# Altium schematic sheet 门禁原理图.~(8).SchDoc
size D
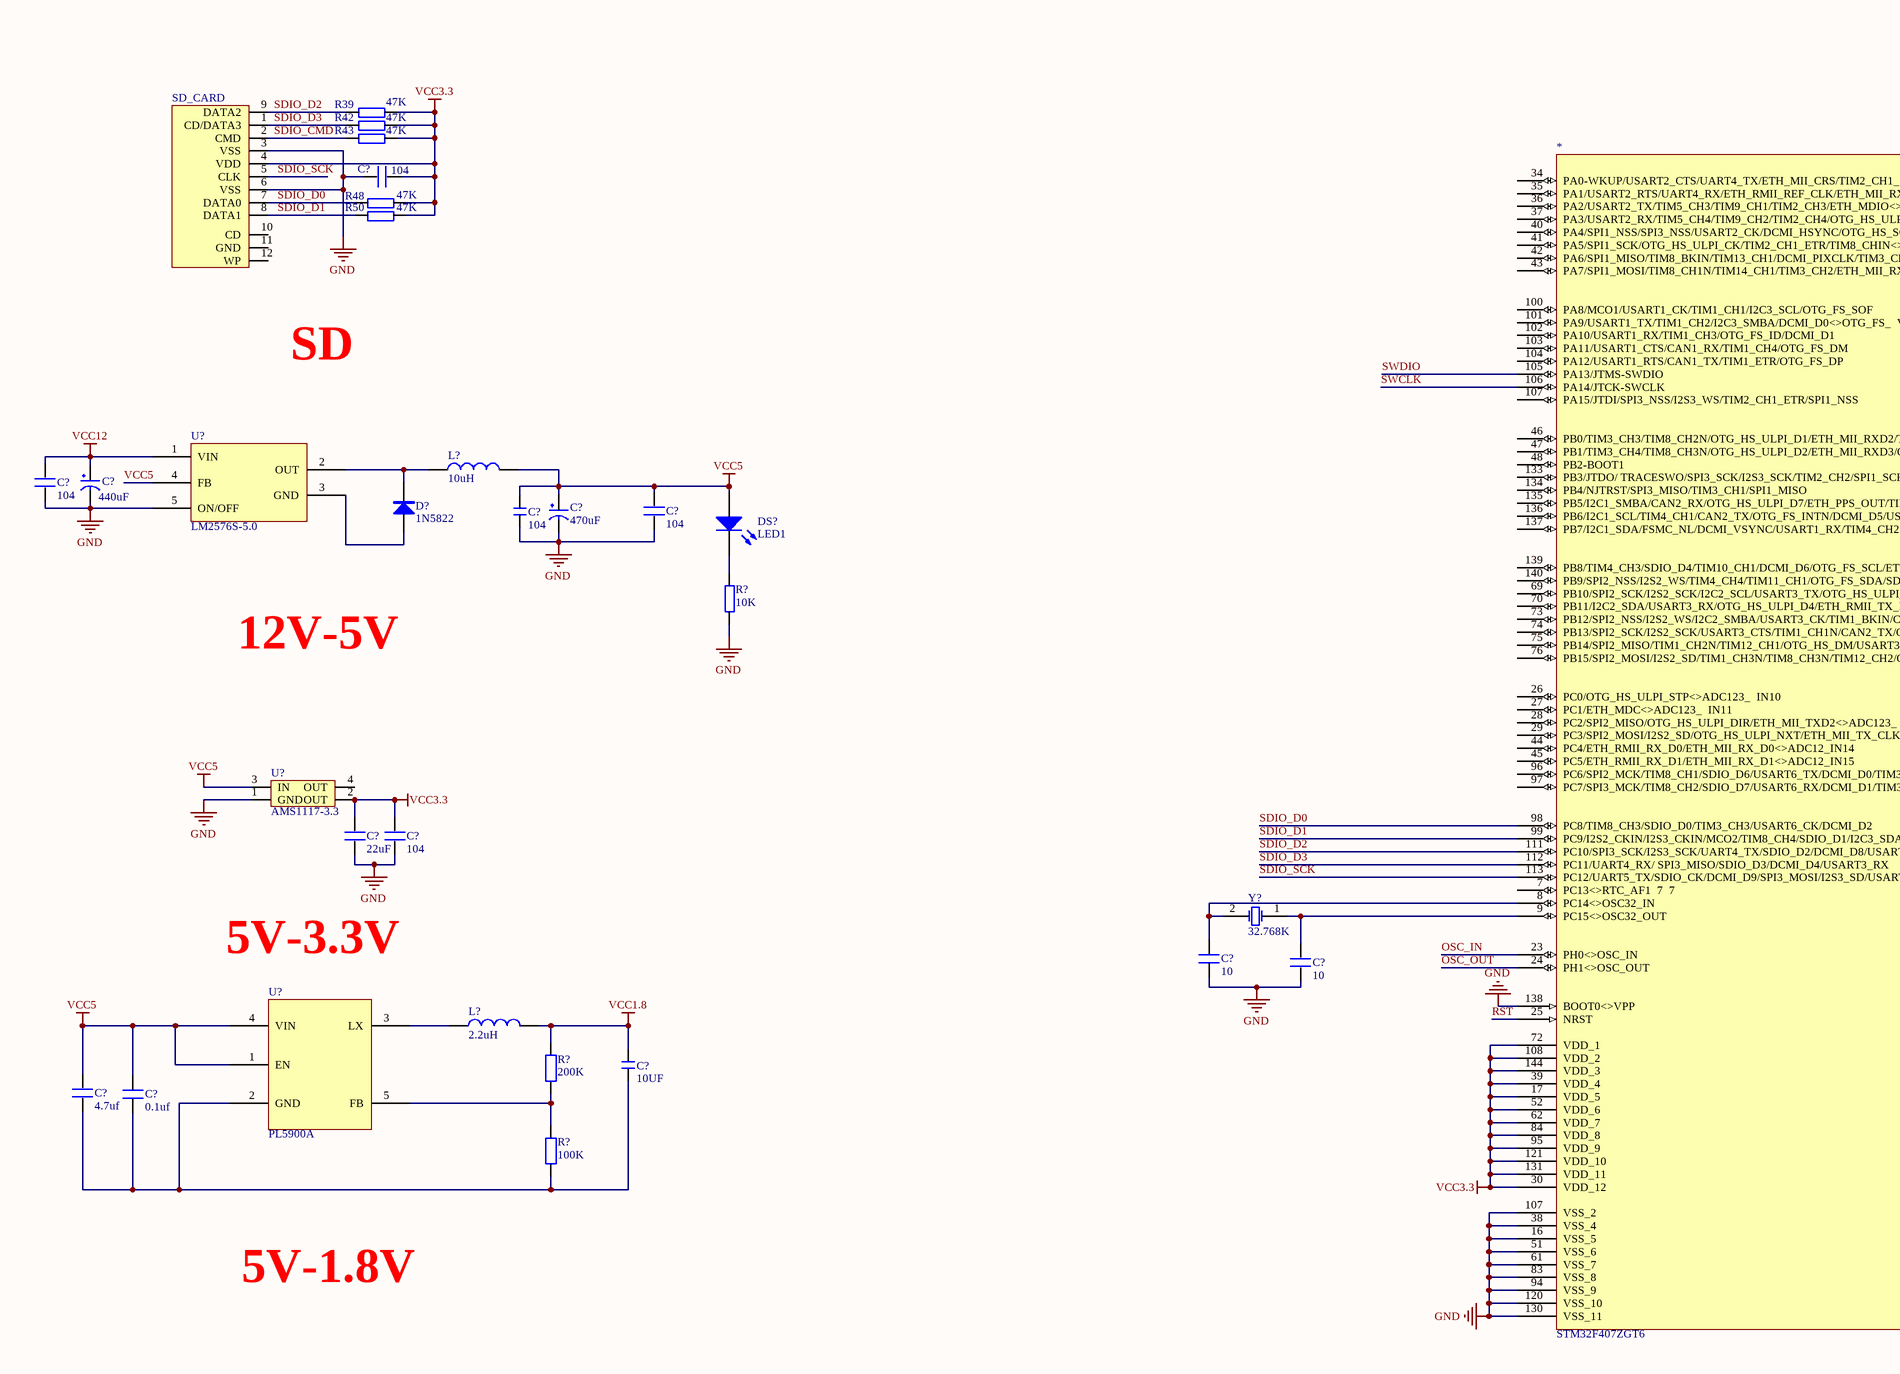
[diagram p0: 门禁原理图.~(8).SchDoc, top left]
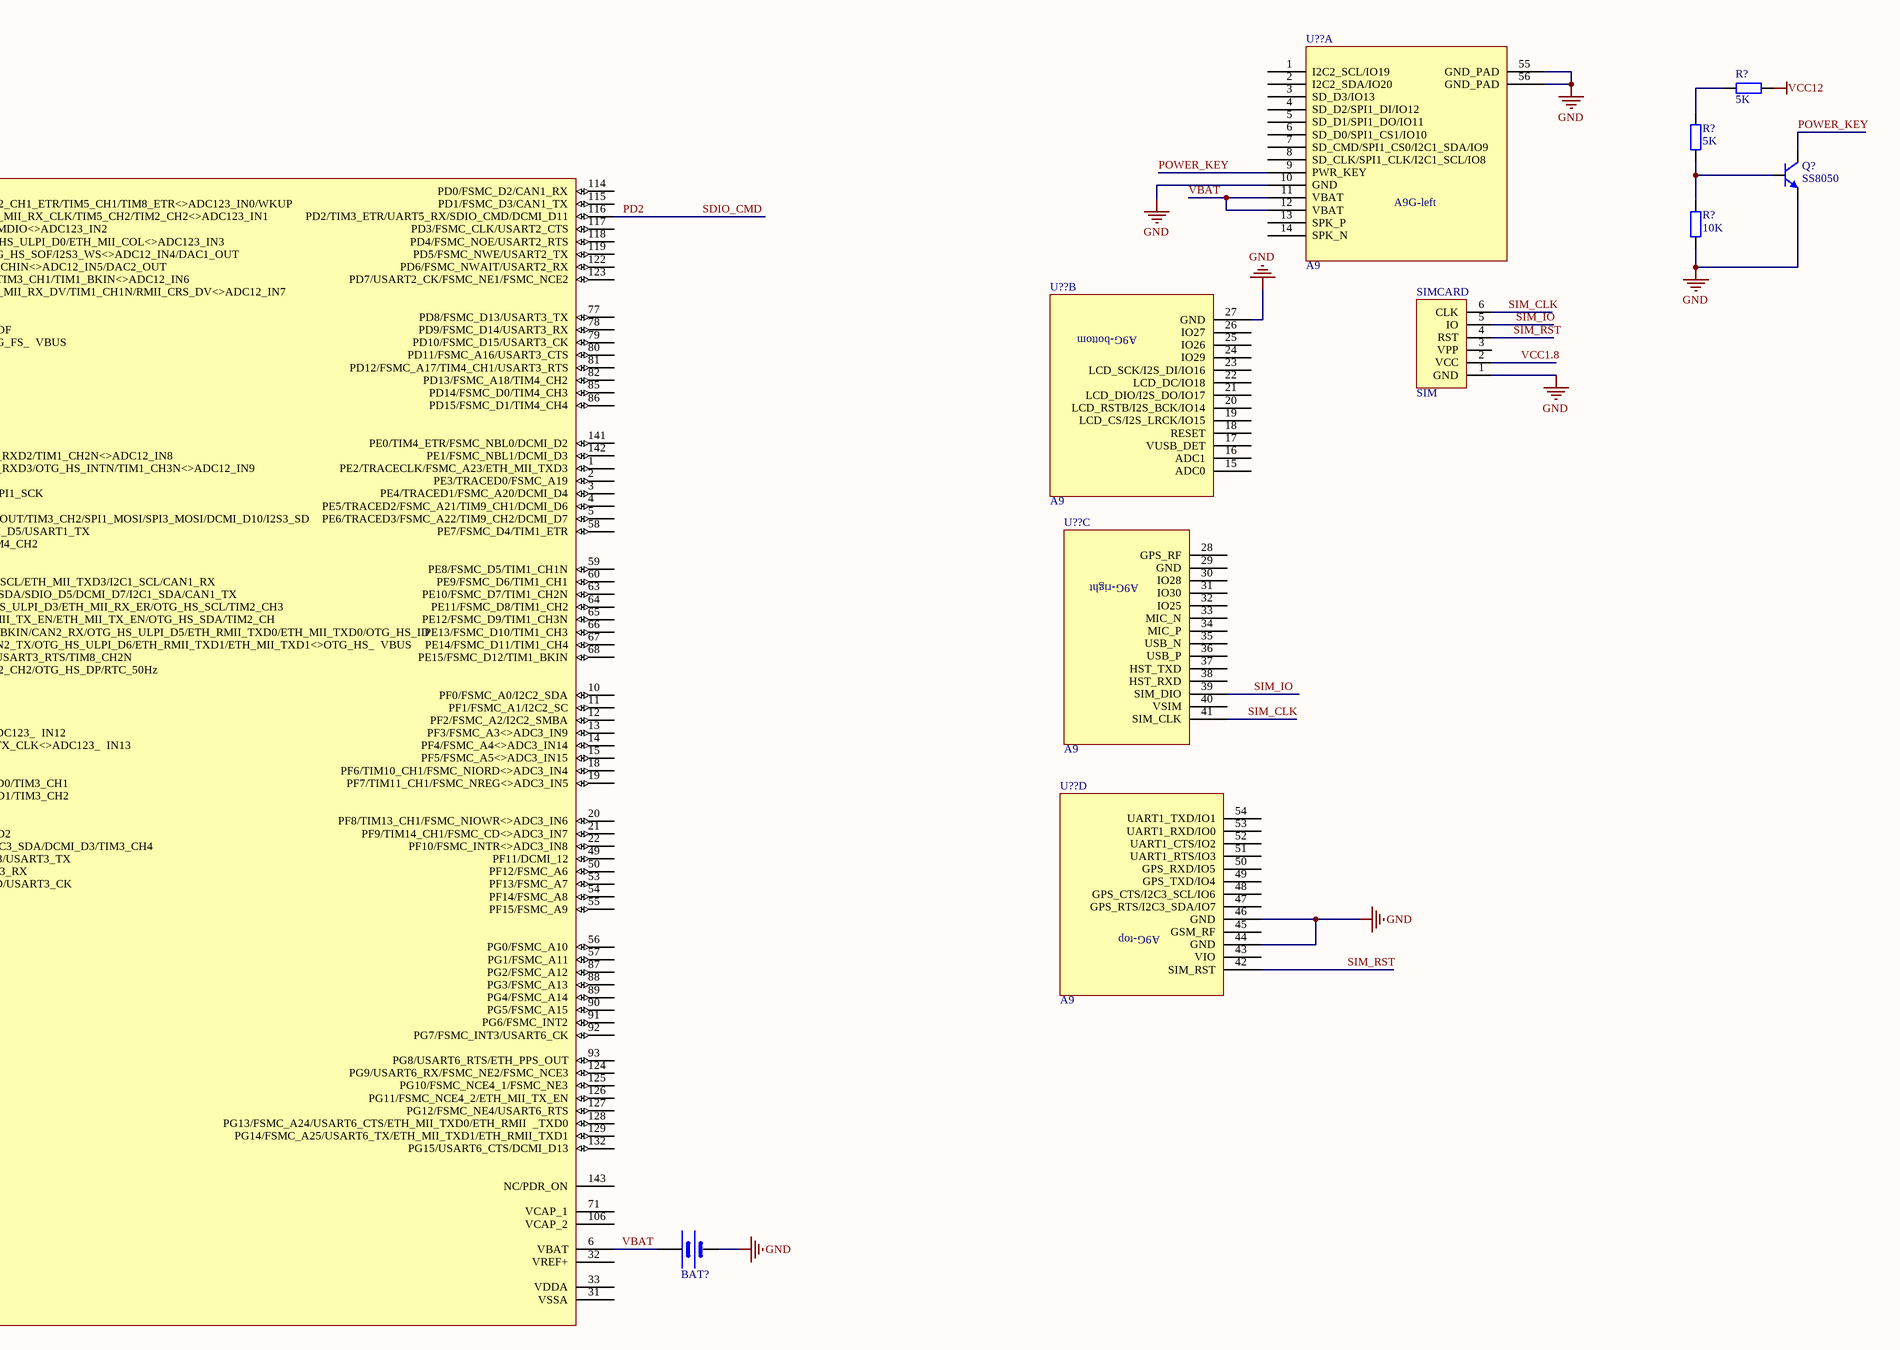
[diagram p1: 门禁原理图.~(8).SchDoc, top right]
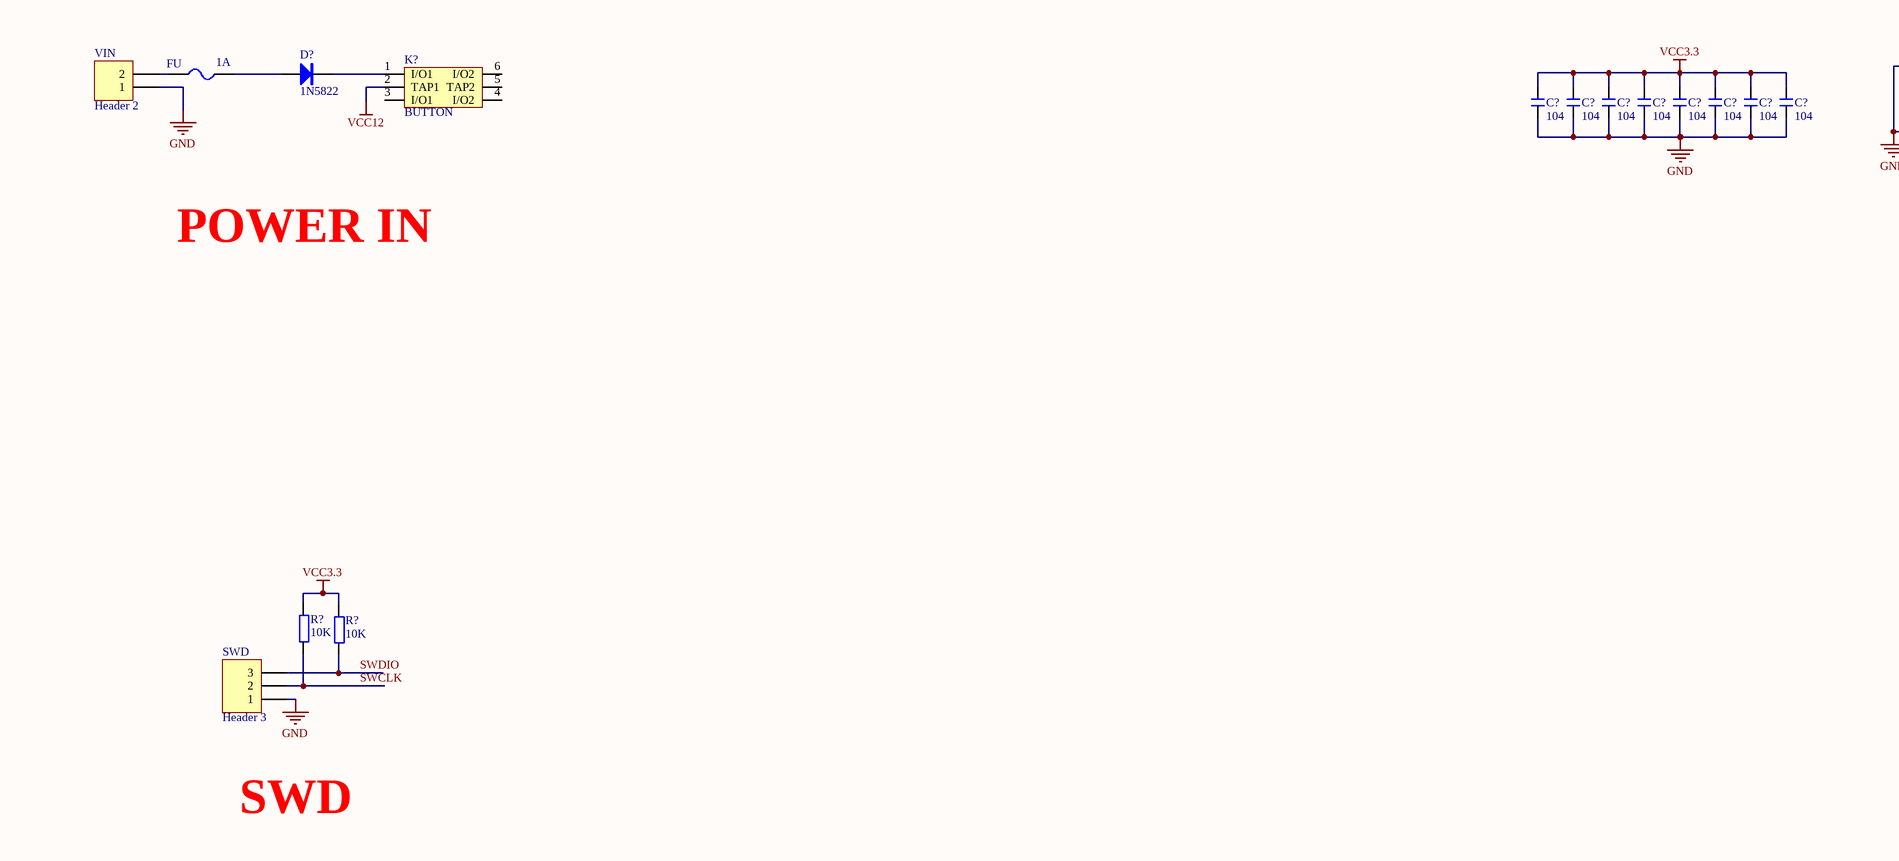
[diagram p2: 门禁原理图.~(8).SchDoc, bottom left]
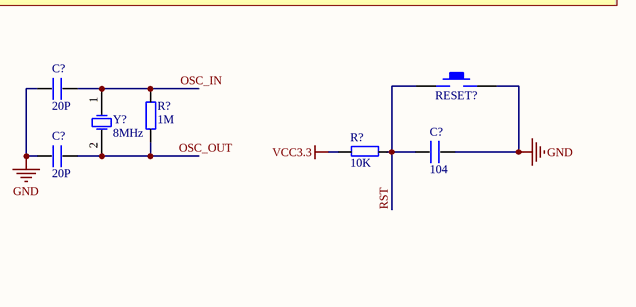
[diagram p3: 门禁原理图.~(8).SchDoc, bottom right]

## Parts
(Parts that share a designator on the sheet are numbered #1, #2 ... from top to bottom, then left to right.)
*  STM32F407ZGT6
BAT?  BATT  [BATM]  (value not drawn)
C?#1  104  [0603P]
C?#2  440uF  [CC6.56.5]
C?#3  104  [C 0805_L]
C?#4  470uF  [CC6.56.5]
C?#5  104  [0603P]
C?#6  104  [0805]
C?#7  10  [0603P]
C?#8  22uF  [0603P]
C?#9  104  [0603P]
C?#10  10  [0603P]
C?#11  10UF  [C 0805_L]
C?#12  4.7uf  [0603P]
C?#13  0.1uf  [0603P]
C?#14  20P  [0805]
C?#15  20P  [0805]
C?#16  104  [C 0805_L]
C?#17  104  [C 0805_L]
C?#18  104  [C 0805_L]
C?#19  104  [C 0805_L]
C?#20  104  [C 0805_L]
C?#21  104  [C 0805_L]
C?#22  104  [C 0805_L]
C?#23  104  [C 0805_L]
C?#24  104  [0805]
D?#1  1N5822  [DIODE_3*5.3]
D?#2  1N5822  [DIODE_3*5.3]
DS?  LED1  [SMDLED]
FU  1A  [FU 1812]
K?  BUTTON  [BTN8.5*8.5]
L?#1  10uH  [L 0805]
L?#2  2.2uH  [L 0805]
Q?  SS8050  [SOT23-3N]
R39  47K  [0603P]
R42  47K  [0603P]
R43  47K  [0603P]
R48  47K  [0603P]
R50  47K  [0603P]
R?#1  5K  [R 0805_L]
R?#2  5K  [R 0805_L]
R?#3  10K  [R 0805_L]
R?#4  10K  [0805]
R?#5  200K  [R 0805_L]
R?#6  100K  [R 0805_L]
R?#7  10K  [0805]
R?#8  1M  [0805]
R?#9  10K  [0805]
R?#10  10K  [0805]
RESET?  KEY_M  [KEY_M]  (value not drawn)
SD_CARD  sd card  [SDCARD_L]  (value not drawn)
SIMCARD  SIM  [MICRO SIM]
SWD  Header 3  [HDR1X3]
U?#1  LM2576S-5.0  [TO263-5A]
U?#2  AMS1117-3.3  [AMS1117]
U?#3  PL5900A  [SOT23-5L]
U??#1  A9  [A9]  (part A of 4)
U??#2  A9  [A9]  (part B of 4)
U??#3  A9  [A9]  (part C of 4)
U??#4  A9  [A9]  (part D of 4)
VIN  Header 2  [HDR1X2]
Y?#1  32.768K  [XTAL32]
Y?#2  8MHz  [XTAL_US]

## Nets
GND: *.16(VSS_5) *.38(VSS_4) *.51(VSS_6) *.61(VSS_7) *.83(VSS_8) *.94(VSS_9) *.107(PA15/JTDI/SPI3_NSS/I2S3_WS/TIM2_CH1_ETR/SPI1_NSS) *.120(VSS_10) *.130(VSS_11) *.138(BOOT0<>VPP) BAT?.2(GND) C?#1.1 C?#2.2(GND) C?#3.1 C?#4.2(GND) C?#5.1 C?#6.1 C?#7.2 C?#8.1 C?#9.1 C?#10.1 C?#14.1 C?#15.1 C?#16.1 C?#17.1 C?#18.1 C?#19.1 C?#20.1 C?#21.1 C?#22.1 C?#23.1 C?#24.1 Q?.2(E) R?#3.1 R?#4.1 RESET?.2 SD_CARD.3(VSS) SD_CARD.6(VSS) SIMCARD.1(GND) SWD.1 U?#1.5(ON/OFF) U?#2.1(GND) U??#1.10(GND) U??#1.55(GND_PAD) U??#1.56(GND_PAD) U??#2.27(GND) U??#4.44(GND) U??#4.46(GND) VIN.1
VCC1.8: C?#11.2 L?#2.2 R?#5.2 SIMCARD.2(VCC)
VCC3.3: *.17(VDD_5) *.30(VDD_12) *.39(VDD_4) *.52(VDD_6) *.62(VDD_7) *.72(VDD_1) *.84(VDD_8) *.95(VDD_9) *.108(VDD_2) *.121(VDD_10) *.131(VDD_11) *.144(VDD_3) C?#1.2 C?#8.2 C?#9.2 C?#16.2 C?#17.2 C?#18.2 C?#19.2 C?#20.2 C?#21.2 C?#22.2 C?#23.2 R39.2 R42.2 R43.2 R48.2 R50.2 R?#7.2 R?#9.2 R?#10.2 SD_CARD.4(VDD) U?#2.2(OUT)
VCC5: C?#3.2 C?#4.1(VCC) C?#6.2 C?#12.2 C?#13.2 DS?.1(A) L?#1.2 U?#1.4(FB) U?#2.3(IN) U?#3.1(EN) U?#3.4(VIN)
VCC12: C?#2.1(VCC) C?#5.2 K?.2(TAP1) R?#1.1 U?#1.1(VIN)
OSC_IN: *.23(PH0<>OSC_IN) C?#14.2 R?#8.2 Y?#2.1(OSC1)
OSC_OUT: *.24(PH1<>OSC_OUT) C?#15.2 R?#8.1 Y?#2.2(OSC2)
PD2: *.116(PD2/TIM3_ETR/UART5_RX/SDIO_CMD/DCMI_D11) R43.1 SD_CARD.2(CMD)  [also labelled SDIO_CMD]
POWER_KEY: Q?.3(C) U??#1.9(PWR_KEY)
RST: *.25(NRST) C?#24.2 R?#7.1 RESET?.1
SDIO_D0: *.98(PC8/TIM8_CH3/SDIO_D0/TIM3_CH3/USART6_CK/DCMI_D2) R48.1 SD_CARD.7(DATA0)
SDIO_D1: *.99(PC9/I2S2_CKIN/I2S3_CKIN/MCO2/TIM8_CH4/SDIO_D1/I2C3_SDA/DCMI_D3/TIM3_CH4) R50.1 SD_CARD.8(DATA1)
SDIO_D2: *.111(PC10/SPI3_SCK/I2S3_SCK/UART4_TX/SDIO_D2/DCMI_D8/USART3_TX) R39.1 SD_CARD.9(DATA2)
SDIO_D3: *.112(PC11/UART4_RX/_SPI3_MISO/SDIO_D3/DCMI_D4/USART3_RX) R42.1 SD_CARD.1(CD/DATA3)
SDIO_SCK: *.113(PC12/UART5_TX/SDIO_CK/DCMI_D9/SPI3_MOSI/I2S3_SD/USART3_CK) SD_CARD.5(CLK)
SIM_CLK: SIMCARD.6(CLK) U??#3.41(SIM_CLK)
SIM_IO: SIMCARD.5(IO) U??#3.39(SIM_DIO)
SIM_RST: SIMCARD.4(RST) U??#4.42(SIM_RST)
SWCLK: *.106(PA14/JTCK-SWCLK) R?#9.1 SWD.2
SWDIO: *.105(PA13/JTMS-SWDIO) R?#10.1 SWD.3
VBAT: *.6(VBAT) BAT?.1(VCC) U??#1.11(VBAT) U??#1.12(VBAT)
Net*_8: *.8(PC14<>OSC32_IN) C?#7.1 Y?#1.2(OSC2)
Net*_9: *.9(PC15<>OSC32_OUT) C?#10.2 Y?#1.1(OSC1)
NetC?#11_1: C?#11.1 C?#12.1 C?#13.1 R?#6.1 U?#3.2(GND)
NetD?#1_1: D?#1.1(A) U?#1.3(GND)
NetD?#1_2: D?#1.2(K) L?#1.1 U?#1.2(OUT)
NetD?#2_1: D?#2.1(A) FU.2
NetD?#2_2: D?#2.2(K) K?.1(I/O1)
NetDS?_2: DS?.2(K) R?#4.2
NetFU_1: FU.1 VIN.2
NetL?#2_1: L?#2.1 U?#3.3(LX)
NetQ?_1: Q?.1(B) R?#2.1 R?#3.2
NetR?#1_2: R?#1.2 R?#2.2
NetR?#5_1: R?#5.1 R?#6.2 U?#3.5(FB)

Not connected (* = marked no-connect by the designer): * 1(PE2/TRACECLK/FSMC_A23/ETH_MII_TXD3) 2(PE3/TRACED0/FSMC_A19) 3(PE4/TRACED1/FSMC_A20/DCMI_D4) 4(PE5/TRACED2/FSMC_A21/TIM9_CH1/DCMI_D6) 5(PE6/TRACED3/FSMC_A22/TIM9_CH2/DCMI_D7) 7(PC13<>RTC_AF1__7__7) 10(PF0/FSMC_A0/I2C2_SDA) 11(PF1/FSMC_A1/I2C2_SC) 12(PF2/FSMC_A2/I2C2_SMBA) 13(PF3/FSMC_A3<>ADC3_IN9) 14(PF4/FSMC_A4<>ADC3_IN14) 15(PF5/FSMC_A5<>ADC3_IN15) 18(PF6/TIM10_CH1/FSMC_NIORD<>ADC3_IN4) 19(PF7/TIM11_CH1/FSMC_NREG<>ADC3_IN5) 20(PF8/TIM13_CH1/FSMC_NIOWR<>ADC3_IN6) 21(PF9/TIM14_CH1/FSMC_CD<>ADC3_IN7) 22(PF10/FSMC_INTR<>ADC3_IN8) 26(PC0/OTG_HS_ULPI_STP<>ADC123___IN10) 27(PC1/ETH_MDC<>ADC123___IN11) 28(PC2/SPI2_MISO/OTG_HS_ULPI_DIR/ETH_MII_TXD2<>ADC123___IN12) 29(PC3/SPI2_MOSI/I2S2_SD/OTG_HS_ULPI_NXT/ETH_MII_TX_CLK<>ADC123___IN13) 31(VSSA) 32(VREF+) 33(VDDA) 34(PA0-WKUP/USART2_CTS/UART4_TX/ETH_MII_CRS/TIM2_CH1_ETR/TIM5_CH1/TIM8_ETR<>ADC123_IN0/WKUP) 35(PA1/USART2_RTS/UART4_RX/ETH_RMII_REF_CLK/ETH_MII_RX_CLK/TIM5_CH2/TIM2_CH2<>ADC123_IN1) 36(PA2/USART2_TX/TIM5_CH3/TIM9_CH1/TIM2_CH3/ETH_MDIO<>ADC123_IN2) 37(PA3/USART2_RX/TIM5_CH4/TIM9_CH2/TIM2_CH4/OTG_HS_ULPI_D0/ETH_MII_COL<>ADC123_IN3) 40(PA4/SPI1_NSS/SPI3_NSS/USART2_CK/DCMI_HSYNC/OTG_HS_SOF/I2S3_WS<>ADC12_IN4/DAC1_OUT) 41(PA5/SPI1_SCK/OTG_HS_ULPI_CK/TIM2_CH1_ETR/TIM8_CHIN<>ADC12_IN5/DAC2_OUT) 42(PA6/SPI1_MISO/TIM8_BKIN/TIM13_CH1/DCMI_PIXCLK/TIM3_CH1/TIM1_BKIN<>ADC12_IN6) 43(PA7/SPI1_MOSI/TIM8_CH1N/TIM14_CH1/TIM3_CH2/ETH_MII_RX_DV/TIM1_CH1N/RMII_CRS_DV<>ADC12_IN7) 44(PC4/ETH_RMII_RX_D0/ETH_MII_RX_D0<>ADC12_IN14) 45(PC5/ETH_RMII_RX_D1/ETH_MII_RX_D1<>ADC12_IN15) 46(PB0/TIM3_CH3/TIM8_CH2N/OTG_HS_ULPI_D1/ETH_MII_RXD2/TIM1_CH2N<>ADC12_IN8) 47(PB1/TIM3_CH4/TIM8_CH3N/OTG_HS_ULPI_D2/ETH_MII_RXD3/OTG_HS_INTN/TIM1_CH3N<>ADC12_IN9) 48(PB2-BOOT1) 49(PF11/DCMI_12) 50(PF12/FSMC_A6) 53(PF13/FSMC_A7) 54(PF14/FSMC_A8) 55(PF15/FSMC_A9) 56(PG0/FSMC_A10) 57(PG1/FSMC_A11) 58(PE7/FSMC_D4/TIM1_ETR) 59(PE8/FSMC_D5/TIM1_CH1N) 60(PE9/FSMC_D6/TIM1_CH1) 63(PE10/FSMC_D7/TIM1_CH2N) 64(PE11/FSMC_D8/TIM1_CH2) 65(PE12/FSMC_D9/TIM1_CH3N) 66(PE13/FSMC_D10/TIM1_CH3) 67(PE14/FSMC_D11/TIM1_CH4) 68(PE15/FSMC_D12/TIM1_BKIN) 69(PB10/SPI2_SCK/I2S2_SCK/I2C2_SCL/USART3_TX/OTG_HS_ULPI_D3/ETH_MII_RX_ER/OTG_HS_SCL/TIM2_CH3) 70(PB11/I2C2_SDA/USART3_RX/OTG_HS_ULPI_D4/ETH_RMII_TX_EN/ETH_MII_TX_EN/OTG_HS_SDA/TIM2_CH) 71(VCAP_1) 73(PB12/SPI2_NSS/I2S2_WS/I2C2_SMBA/USART3_CK/TIM1_BKIN/CAN2_RX/OTG_HS_ULPI_D5/ETH_RMII_TXD0/ETH_MII_TXD0/OTG_HS_ID) 74(PB13/SPI2_SCK/I2S2_SCK/USART3_CTS/TIM1_CH1N/CAN2_TX/OTG_HS_ULPI_D6/ETH_RMII_TXD1/ETH_MII_TXD1<>OTG_HS___VBUS) 75(PB14/SPI2_MISO/TIM1_CH2N/TIM12_CH1/OTG_HS_DM/USART3_RTS/TIM8_CH2N) 76(PB15/SPI2_MOSI/I2S2_SD/TIM1_CH3N/TIM8_CH3N/TIM12_CH2/OTG_HS_DP/RTC_50Hz) 77(PD8/FSMC_D13/USART3_TX) 78(PD9/FSMC_D14/USART3_RX) 79(PD10/FSMC_D15/USART3_CK) 80(PD11/FSMC_A16/USART3_CTS) 81(PD12/FSMC_A17/TIM4_CH1/USART3_RTS) 82(PD13/FSMC_A18/TIM4_CH2) 85(PD14/FSMC_D0/TIM4_CH3) 86(PD15/FSMC_D1/TIM4_CH4) 87(PG2/FSMC_A12) 88(PG3/FSMC_A13) 89(PG4/FSMC_A14) 90(PG5/FSMC_A15) 91(PG6/FSMC_INT2) 92(PG7/FSMC_INT3/USART6_CK) 93(PG8/USART6_RTS/ETH_PPS_OUT) 96(PC6/SPI2_MCK/TIM8_CH1/SDIO_D6/USART6_TX/DCMI_D0/TIM3_CH1) 97(PC7/SPI3_MCK/TIM8_CH2/SDIO_D7/USART6_RX/DCMI_D1/TIM3_CH2) 100(PA8/MCO1/USART1_CK/TIM1_CH1/I2C3_SCL/OTG_FS_SOF) 101(PA9/USART1_TX/TIM1_CH2/I2C3_SMBA/DCMI_D0<>OTG_FS___VBUS) 102(PA10/USART1_RX/TIM1_CH3/OTG_FS_ID/DCMI_D1) 103(PA11/USART1_CTS/CAN1_RX/TIM1_CH4/OTG_FS_DM) 104(PA12/USART1_RTS/CAN1_TX/TIM1_ETR/OTG_FS_DP) 114(PD0/FSMC_D2/CAN1_RX) 115(PD1/FSMC_D3/CAN1_TX) 117(PD3/FSMC_CLK/USART2_CTS) 118(PD4/FSMC_NOE/USART2_RTS) 119(PD5/FSMC_NWE/USART2_TX) 122(PD6/FSMC_NWAIT/USART2_RX) 123(PD7/USART2_CK/FSMC_NE1/FSMC_NCE2) 124(PG9/USART6_RX/FSMC_NE2/FSMC_NCE3) 125(PG10/FSMC_NCE4_1/FSMC_NE3) 126(PG11/FSMC_NCE4_2/ETH_MII_TX_EN) 127(PG12/FSMC_NE4/USART6_RTS) 128(PG13/FSMC_A24/USART6_CTS/ETH_MII_TXD0/ETH_RMII___TXD0) 129(PG14/FSMC_A25/USART6_TX/ETH_MII_TXD1/ETH_RMII_TXD1) 132(PG15/USART6_CTS/DCMI_D13) 133(PB3/JTDO/_TRACESWO/SPI3_SCK/I2S3_SCK/TIM2_CH2/SPI1_SCK) 134(PB4/NJTRST/SPI3_MISO/TIM3_CH1/SPI1_MISO) 135(PB5/I2C1_SMBA/CAN2_RX/OTG_HS_ULPI_D7/ETH_PPS_OUT/TIM3_CH2/SPI1_MOSI/SPI3_MOSI/DCMI_D10/I2S3_SD) 136(PB6/I2C1_SCL/TIM4_CH1/CAN2_TX/OTG_FS_INTN/DCMI_D5/USART1_TX) 137(PB7/I2C1_SDA/FSMC_NL/DCMI_VSYNC/USART1_RX/TIM4_CH2) 139(PB8/TIM4_CH3/SDIO_D4/TIM10_CH1/DCMI_D6/OTG_FS_SCL/ETH_MII_TXD3/I2C1_SCL/CAN1_RX) 140(PB9/SPI2_NSS/I2S2_WS/TIM4_CH4/TIM11_CH1/OTG_FS_SDA/SDIO_D5/DCMI_D7/I2C1_SDA/CAN1_TX) 141(PE0/TIM4_ETR/FSMC_NBL0/DCMI_D2) 142(PE1/FSMC_NBL1/DCMI_D3) 143(NC/PDR_ON); K? 3(I/O1) 4(I/O2) 5(TAP2) 6(I/O2); SD_CARD 10(CD) 11(GND) 12(WP); SIMCARD 3(VPP); U?#2 4(OUT); U??#1 1(I2C2_SCL/IO19) 2(I2C2_SDA/IO20) 3(SD_D3/IO13) 4(SD_D2/SPI1_DI/IO12) 5(SD_D1/SPI1_DO/IO11) 6(SD_D0/SPI1_CS1/IO10) 7(SD_CMD/SPI1_CS0/I2C1_SDA/IO9) 8(SD_CLK/SPI1_CLK/I2C1_SCL/IO8) 13(SPK_P) 14(SPK_N); U??#2 15(ADC0) 16(ADC1) 17(VUSB_DET) 18(RESET) 19(LCD_CS/I2S_LRCK/IO15) 20(LCD_RSTB/I2S_BCK/IO14) 21(LCD_DIO/I2S_DO/IO17) 22(LCD_DC/IO18) 23(LCD_SCK/I2S_DI/IO16) 24(IO29) 25(IO26) 26(IO27); U??#3 28(GPS_RF) 29(GND) 30(IO28) 31(IO30) 32(IO25) 33(MIC_N) 34(MIC_P) 35(USB_N) 36(USB_P) 37(HST_TXD) 38(HST_RXD) 40(VSIM); U??#4 43(VIO) 45(GSM_RF) 47(GPS_RTS/I2C3_SDA/IO7) 48(GPS_CTS/I2C3_SCL/IO6) 49(GPS_TXD/IO4) 50(GPS_RXD/IO5) 51(UART1_RTS/IO3) 52(UART1_CTS/IO2) 53(UART1_RXD/IO0) 54(UART1_TXD/IO1)

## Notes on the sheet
- SD
- 12V-5V
- 5V-3.3V
- 5V-1.8V
- POWER IN
- SWD

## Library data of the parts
BAT? = BAT
C?#1 C?#5 C?#6 C?#8 C?#9 C?#12 C?#13 = C
C?#2 C?#4 = CAP
C?#3 C?#11 C?#16-C?#23 = C: 无极性贴片电容; 版权归属: 源创客
C?#7 C?#10 = C_2
C?#14 C?#15 = C_3
C?#24 = C_1
D?#1 D?#2 = 1N4148: 高速开关二极管; 版权归属: 源创客
DS? = LED2: Typical RED, GREEN, YELLOW, AMBER GaAs LED
FU = FU: 贴片保险丝; 版权归属: 源创客
L?#1 L?#2 = L: 小功率贴片电感; 版权归属: 源创客
Q? = 8050-SMD: 高频放大-NPN型; 版权归属: 源创客; 属性: 40V 1.5A 1W 100MHZ
R39 R42 R43 R48 R50 R?#4 R?#7 R?#9 R?#10 = R
R?#1-R?#3 R?#5 R?#6 = R: 贴片电阻; 版权归属: 源创客
R?#8 = R_2
SIMCARD = MICRO SIM: SIM卡座; 版权归属: 源创客
SWD = Header 3: Header, 3-Pin
U?#1 = Component_1
U?#2 = AMS1117
VIN = Header 2: Header, 2-Pin
Y?#1 = XTAL_1: Crystal Oscillator
Y?#2 = XTAL: Crystal Oscillator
